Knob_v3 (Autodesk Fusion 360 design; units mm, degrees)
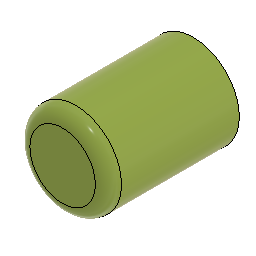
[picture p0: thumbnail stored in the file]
sketch "Sketch1" plane through (0, 0, 0) normal (0, 1, 0) x axis (1, 0, 0)
  circle C1 centre (0, 0) radius 3.5
  point P1 (0, 0)
  point P2 (0, 0)
  coincident P1 P2
  dimension "d1" diameter C1 = 7
extrude "Extrude1" new body sketch "Sketch1" along normal blind 10
fillet "Fillet1" radius 1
